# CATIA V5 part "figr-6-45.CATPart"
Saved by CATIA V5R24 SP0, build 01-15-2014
Part number: Part1
Bounding box of the stored display mesh (mm): x -26.811 to 26.811, y -47.298 to 47.298, z 0 to 31.431
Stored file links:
  D:\KAVITA\CATIA V5-6R2014 Project_ Kavita\CATIA V5-6R2014_partfiles\Partfiles\c06_catia_v5-6r2014_prt\figr-6-45.CATPart
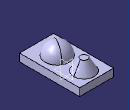
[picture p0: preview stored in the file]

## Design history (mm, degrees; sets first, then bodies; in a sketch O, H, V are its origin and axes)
Body1 (main body)
  Sketch1 on xy-plane, origin (0, 0, 0), H (1, 0, 0), V (0, 1, 0)
    line L1 (-26.8114, 47.2981) -> (26.8114, 47.2981)
    line L2 (26.8114, 47.2981) -> (26.8114, -47.2981)
    line L3 (26.8114, -47.2981) -> (-26.8114, -47.2981)
    line L4 (-26.8114, -47.2981) -> (-26.8114, 47.2981)
    axis line L5 (26.8114, -47.2981) -> (-26.8114, 47.2981)
    horizontal: L1 H, L3 H
    vertical: L2 V, L4 V
    coincidence: L5 O
    midpoint: L5 O
  Pad1: profile Sketch1, direction (0, 0, 1), length 12
  Sketch2 on yz-plane, origin (0, 0, 0), H (0, 1, 0), V (0, 0, 1)
    axis line L1 (-14.846, 35.4307) -> (-14.846, -5.9324)
    arc A1 centre (-14.846, 12.2093) radius 19.2216 from (-14.846, 31.431) to (-33.1926, 6.476) ccw
    point P3 (-14.846, 12.2093)
    point P4 (-14.846, 31.431)
    line L2 (-14.846, 31.431) -> (-14.846, 8.3996)
    line L3 (-14.846, 8.3996) -> (-33.1926, 6.476)
    vertical: L1 V, L2 V
    coincidence: P3 L1, P4 L1, A1 O
  Shaft1: profile Sketch2, axis Sketch2.L1, angle 360
  Sketch3 on face of Pad1, origin (0, 0, 12), H (1, 0, 0), V (0, 1, 0)
    circle A1 centre (0, 27.4246) radius 16.1543
    point P1 (0, 27.4246)
    coincidence: P1 V
  Pad2: profile Sketch3, direction (0, 0, 1), length 18
  Draft1: Angle 30, Neutral face of Pad1, PullDir face of Pad1, SupportToDraft face of Pad2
